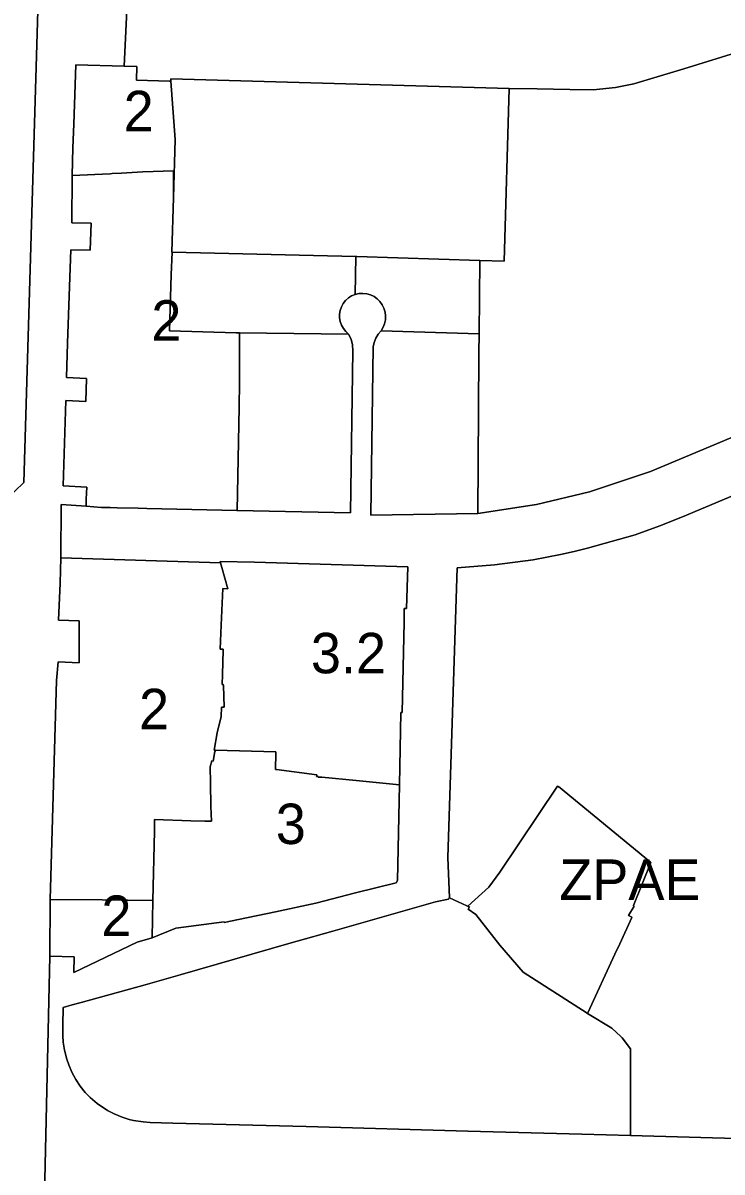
# Model space of a CAD drawing. Extents: x 598968 to 613553, y 4409678 to 4430833.
# Drawn here: x 607715.2 to 607922.7, y 4415445.3 to 4415786.4 of the extents above; entities that cross this region are included whole.
import ezdxf

# ---------------------------------------------------------------- set-up
doc = ezdxf.new("R2010")
doc.units = 0
for name, color, linetype in [('1', 7, 'Continuous'), ('ZONA 2. CARRERS DE CASES. Cases de trast', 7, 'Continuous'), ("ZONA 3. ILLES  D'EDIFICIS ENTRE MITGERES. EIXAMPLE.", 7, 'Continuous'), ('ZONA 3.2. Volumentría específica - ANNEX III B', 7, 'Continuous'), ('Zona de Protecció arquològica-etnoògica', 7, 'Continuous')]:
    doc.layers.add(name, color=color, linetype=linetype)

msp = doc.modelspace()

# ---------------------------------------------------------------- linework, layer by layer
at = {"layer": '1'}
for points in [[(607714.9485, 4415838.4282), (607720.9184, 4415833.4684), (607715.4891, 4415649.9805), (607710.1092, 4415644.8405), (607679.8495, 4415645.5899), (607674.8196, 4415650.8997), (607675.5894, 4415689.7193), (607677.1093, 4415729.6889), (607678.8091, 4415770.7584), (607679.859, 4415798.6881), (607681.1189, 4415834.1777), (607686.7188, 4415839.3877)], [(607850.2624, 4415640.8173), (607867.6185, 4415643.5047), (607883.4383, 4415647.215), (607901.4656, 4415653.2752), (607957.6759, 4415676.7834), (607977.337, 4415685.0662), (607978.3535, 4415685.4948), (607979.827, 4415686.1162), (607979.3077, 4415687.4699), (607939.6372, 4415781.6243), (607929.6005, 4415778.452), (607911.4256, 4415772.8482), (607896.5278, 4415768.3637), (607891.1428, 4415767.2436), (607884.4372, 4415766.6161), (607877.527, 4415766.7217), (607867.8281, 4415766.9182), (607859.5557, 4415766.9957), (607858.0621, 4415715.7316), (607850.8255, 4415715.9577), (607850.5948, 4415694.1575), (607850.5948, 4415694.1535), (607850.5476, 4415688.474), (607850.4452, 4415671.3681)], [(607859.5557, 4415766.9957), (607759.0694, 4415769.8512), (607759.1181, 4415769.1588), (607760.3394, 4415751.7915), (607759.8571, 4415734.5967), (607759.4032, 4415718.4153), (607759.4031, 4415718.4118), (607759.4472, 4415718.4107), (607813.9919, 4415717.107), (607814.2717, 4415717.0994), (607850.8106, 4415715.9582), (607850.8255, 4415715.9577), (607858.0621, 4415715.7316)], [(607813.9919, 4415717.107), (607759.4472, 4415718.4107), (607759.2115, 4415711.6107), (607758.7407, 4415695.0522), (607778.4594, 4415694.4725), (607779.4146, 4415694.4613), (607811.8723, 4415694.0812), (607811.0269, 4415694.8282), (607810.3186, 4415695.7063), (607809.7676, 4415696.6906), (607809.3894, 4415697.7535), (607809.1946, 4415698.8647), (607809.1888, 4415699.9928), (607809.3723, 4415701.1059), (607809.7397, 4415702.1726), (607810.2807, 4415703.1626), (607810.9799, 4415704.0479), (607811.8177, 4415704.8034), (607812.7702, 4415705.4079), (607813.8105, 4415705.8441)], [(607850.8255, 4415715.9577), (607850.8106, 4415715.9582), (607814.2717, 4415717.0994), (607813.9919, 4415717.107), (607813.8105, 4415705.8441), (607814.9448, 4415706.093), (607816.1047, 4415706.1507), (607817.2582, 4415706.0158), (607818.3733, 4415705.6916), (607819.4194, 4415705.1874), (607820.3677, 4415704.5169), (607821.1918, 4415703.6988), (607821.8692, 4415702.7555), (607822.381, 4415701.7131), (607822.7133, 4415700.6003), (607822.8567, 4415699.4479), (607822.8075, 4415698.2877), (607822.5668, 4415697.1516), (607822.1414, 4415696.071), (607821.543, 4415695.0757), (607850.5948, 4415694.1575)], [(607811.8723, 4415694.0812), (607779.4146, 4415694.4613), (607779.414, 4415694.4154), (607779.4894, 4415694.4134), (607779.4429, 4415679.6677), (607779.3983, 4415672.3714), (607778.8384, 4415641.7117), (607778.7075, 4415641.7145), (607778.7069, 4415641.6731), (607812.4293, 4415641.0105), (607813.1772, 4415689.1329), (607813.0335, 4415690.8502), (607812.5941, 4415692.5164)], [(607850.5948, 4415694.1575), (607821.543, 4415695.0757), (607820.6452, 4415694.0359), (607819.935, 4415692.8601), (607819.4325, 4415691.5815), (607819.1521, 4415690.2367), (607818.4838, 4415640.3137), (607850.2624, 4415640.8173), (607850.4452, 4415671.3681), (607850.5476, 4415688.474), (607850.5948, 4415694.1535)], [(607841.8091, 4415526.6614), (607841.6892, 4415526.7156), (607841.5147, 4415526.2931), (607837.7086, 4415525.5441), (607825.8596, 4415522.1511), (607807.1774, 4415516.834), (607796.6484, 4415513.7925), (607794.1727, 4415513.084), (607761.8213, 4415503.8268), (607751.4964, 4415500.8964), (607732.4577, 4415495.6232), (607729.8331, 4415494.8962), (607727.139, 4415494.15), (607726.994, 4415488.8423), (607727.0498, 4415487.2224), (607727.0513, 4415485.7209), (607727.1748, 4415483.8285), (607727.5235, 4415481.4596), (607728.1793, 4415478.8123), (607728.7794, 4415477.0565), (607729.677, 4415474.9753), (607730.9118, 4415472.708), (607732.2131, 4415470.7706), (607733.7103, 4415468.921), (607735.1613, 4415467.4093), (607737.2501, 4415465.5989), (607740.3061, 4415463.5422), (607742.2788, 4415462.5132), (607744.6516, 4415461.5368), (607746.7199, 4415460.8947), (607748.0225, 4415460.583), (607750.9173, 4415460.1328), (607753.0081, 4415460.0083), (607759.7376, 4415459.8246), (607799.272, 4415458.7451), (607847.2243, 4415457.4357), (607881.1347, 4415456.5097), (607895.5419, 4415456.1136), (607895.5433, 4415481.8895), (607893.0988, 4415485.1171), (607892.7279, 4415485.4795), (607890.0388, 4415488.017), (607882.8078, 4415492.3427), (607882.6799, 4415492.4192), (607863.689, 4415504.5863), (607856.8012, 4415512.6671), (607849.6392, 4415521.7158), (607847.3692, 4415523.3558), (607847.7192, 4415523.9958), (607847.5739, 4415524.06), (607847.2749, 4415524.1922), (607846.9408, 4415524.34)]]:
    msp.add_lwpolyline(points, close=True, dxfattribs=at)
for points in [[(607720.8462, 4415403.14), (607723.2095, 4415509.3223), (607723.2794, 4415526.2021), (607725.1992, 4415591.1814), (607725.6692, 4415596.8013), (607731.8431, 4415596.4696), (607731.902, 4415608.9244), (607725.7891, 4415609.0912), (607726.1991, 4415620.101), (607726.4194, 4415627.6606), (607726.5133, 4415643.4598), (607733.9189, 4415642.9509), (607733.9911, 4415645.0097), (607734.1189, 4415648.6508), (607727.139, 4415649.0407), (607727.9389, 4415674.3504), (607733.8608, 4415674.0016), (607734.0788, 4415680.8605), (607728.1388, 4415681.1304), (607728.3988, 4415691.4002), (607729.0011, 4415708.1973), (607729.3601, 4415719.0602), (607735.1701, 4415719.0022), (607735.4184, 4415726.9878), (607729.6887, 4415727.1298), (607729.8386, 4415741.1196), (607729.9586, 4415749.3295), (607730.2686, 4415756.3995), (607730.5185, 4415762.2594), (607730.8785, 4415773.9893), (607745.2756, 4415773.6219), (607745.9995, 4415790.2407)], [(607745.9995, 4415790.2407), (607745.2756, 4415773.6219), (607749.0029, 4415773.5268), (607748.8778, 4415769.4693), (607758.7482, 4415769.1498), (607759.1181, 4415769.1588), (607759.0694, 4415769.8512), (607859.5557, 4415766.9957), (607867.8281, 4415766.9182), (607877.527, 4415766.7217), (607884.4372, 4415766.6161), (607891.1428, 4415767.2436), (607896.5278, 4415768.3637), (607911.4256, 4415772.8482), (607929.6005, 4415778.452)], [(607957.6759, 4415676.7834), (607901.4656, 4415653.2752), (607883.4383, 4415647.215), (607867.6185, 4415643.5047), (607850.2624, 4415640.8173), (607818.4838, 4415640.3137), (607819.1521, 4415690.2367), (607819.4325, 4415691.5815), (607819.935, 4415692.8601), (607820.6452, 4415694.0359), (607821.543, 4415695.0757), (607822.1414, 4415696.071), (607822.5668, 4415697.1516), (607822.8075, 4415698.2877), (607822.8567, 4415699.4479), (607822.7133, 4415700.6003), (607822.381, 4415701.7131), (607821.8692, 4415702.7555), (607821.1918, 4415703.6988), (607820.3677, 4415704.5169), (607819.4194, 4415705.1874), (607818.3733, 4415705.6916), (607817.2582, 4415706.0158), (607816.1047, 4415706.1507), (607814.9448, 4415706.093), (607813.8105, 4415705.8441), (607812.7702, 4415705.4079), (607811.8177, 4415704.8034), (607810.9799, 4415704.0479), (607810.2807, 4415703.1626), (607809.7397, 4415702.1726), (607809.3723, 4415701.1059), (607809.1888, 4415699.9928), (607809.1946, 4415698.8647), (607809.3894, 4415697.7535), (607809.7676, 4415696.6906), (607810.3186, 4415695.7063), (607811.0269, 4415694.8282), (607811.8723, 4415694.0812), (607812.5941, 4415692.5164), (607813.0335, 4415690.8502), (607813.1772, 4415689.1329), (607812.4293, 4415641.0105), (607778.7069, 4415641.6731), (607778.7075, 4415641.7145), (607751.9387, 4415642.2812), (607749.3987, 4415642.3612), (607743.1888, 4415642.5011), (607741.0788, 4415642.541), (607738.5189, 4415642.601), (607733.9189, 4415642.9509), (607726.5133, 4415643.4598), (607726.4194, 4415627.6606), (607773.8654, 4415626.1772), (607773.7723, 4415626.5077), (607783.9282, 4415626.3198), (607829.4189, 4415624.9979), (607829.0682, 4415612.5473), (607828.3297, 4415612.5839), (607828.349, 4415608.4981), (607827.7291, 4415581.7184), (607827.4091, 4415581.7184), (607826.9662, 4415560.1971), (607826.3682, 4415531.8139), (607826.0282, 4415531.1139), (607813.9684, 4415528.1837), (607802.1185, 4415525.1035), (607790.2087, 4415522.4834), (607779.1692, 4415520.2224), (607774.9488, 4415519.3431), (607774.9188, 4415519.6031), (607760.559, 4415517.6729), (607753.5391, 4415514.8028), (607749.1292, 4415513.5427), (607730.2594, 4415504.5525), (607730.4094, 4415509.1624), (607723.2095, 4415509.3223), (607720.8462, 4415403.14)], [(608010.5843, 4415452.8771), (607895.5419, 4415456.1136), (607881.1347, 4415456.5097), (607847.2243, 4415457.4357), (607799.272, 4415458.7451), (607759.7376, 4415459.8246), (607753.0081, 4415460.0083), (607750.9173, 4415460.1328), (607748.0225, 4415460.583), (607746.7199, 4415460.8947), (607744.6516, 4415461.5368), (607742.2788, 4415462.5132), (607740.3061, 4415463.5422), (607737.2501, 4415465.5989), (607735.1613, 4415467.4093), (607733.7103, 4415468.921), (607732.2131, 4415470.7706), (607730.9118, 4415472.708), (607729.677, 4415474.9753), (607728.7794, 4415477.0565), (607728.1793, 4415478.8123), (607727.5235, 4415481.4596), (607727.1748, 4415483.8285), (607727.0513, 4415485.7209), (607727.0498, 4415487.2224), (607726.994, 4415488.8423), (607727.139, 4415494.15), (607729.8331, 4415494.8962), (607732.4577, 4415495.6232), (607751.4964, 4415500.8964), (607761.8213, 4415503.8268), (607794.1727, 4415513.084), (607796.6484, 4415513.7925), (607807.1774, 4415516.834), (607825.8596, 4415522.1511), (607837.7086, 4415525.5441), (607841.5147, 4415526.2931), (607841.6892, 4415526.7156), (607841.8091, 4415526.6614), (607841.8092, 4415526.6656), (607841.3392, 4415538.6455), (607844.0589, 4415624.6545), (607855.1687, 4415625.5247), (607866.6686, 4415627.0449), (607874.7733, 4415628.6307), (607878.8224, 4415629.4766), (607882.8284, 4415630.4701), (607896.9382, 4415634.4704), (607904.3046, 4415637.104), (607911.018, 4415639.8355), (607986.087, 4415671.3665)], [(607986.087, 4415671.3665), (607911.018, 4415639.8355), (607904.3046, 4415637.104), (607896.9382, 4415634.4704), (607882.8284, 4415630.4701), (607878.8224, 4415629.4766), (607874.7733, 4415628.6307), (607866.6686, 4415627.0449), (607855.1687, 4415625.5247), (607844.0589, 4415624.6545), (607841.3392, 4415538.6455), (607841.8092, 4415526.6656), (607841.8091, 4415526.6614), (607846.9408, 4415524.34), (607847.2749, 4415524.1922), (607853.4781, 4415529.847), (607856.7414, 4415534.2892), (607873.8877, 4415559.827), (607874.1406, 4415559.6193), (607874.1987, 4415559.7058), (607901.5408, 4415537.2536), (607901.5258, 4415537.2166), (607901.5797, 4415537.1723), (607896.4108, 4415524.4253), (607896.3941, 4415524.3842), (607896.5607, 4415524.2632), (607896.621, 4415524.2194), (607895.0161, 4415521.4282), (607895.9186, 4415520.9267), (607895.8971, 4415520.88), (607895.9574, 4415520.8453), (607892.3575, 4415513.0421), (607890.9241, 4415509.9352), (607882.9198, 4415492.5855), (607882.8078, 4415492.3427), (607890.0388, 4415488.017), (607892.7279, 4415485.4795), (607893.0988, 4415485.1171), (607895.5433, 4415481.8895), (607895.5419, 4415456.1136), (608010.5843, 4415452.8771)]]:
    msp.add_lwpolyline(points, dxfattribs=at)
at = {"layer": 'ZONA 2. CARRERS DE CASES. Cases de trast'}
for points in [[(607745.2756, 4415773.6219), (607730.8785, 4415773.9893), (607730.5185, 4415762.2594), (607730.2686, 4415756.3995), (607729.9586, 4415749.3295), (607729.8386, 4415741.1196), (607741.0785, 4415741.6898), (607741.6886, 4415741.7238), (607744.4884, 4415741.8799), (607750.7684, 4415742.2), (607759.8679, 4415742.5132), (607759.8571, 4415734.5967), (607760.3394, 4415751.7915), (607759.1181, 4415769.1588), (607758.7482, 4415769.1498), (607748.8778, 4415769.4693), (607749.0029, 4415773.5268)], [(607759.8571, 4415734.5967), (607759.8679, 4415742.5132), (607750.7684, 4415742.2), (607744.4884, 4415741.8799), (607741.6886, 4415741.7238), (607741.0785, 4415741.6898), (607729.8386, 4415741.1196), (607729.6887, 4415727.1298), (607735.4184, 4415726.9878), (607735.1701, 4415719.0022), (607729.3601, 4415719.0602), (607729.0011, 4415708.1973), (607728.3988, 4415691.4002), (607728.1388, 4415681.1304), (607734.0788, 4415680.8605), (607733.8608, 4415674.0016), (607727.9389, 4415674.3504), (607727.139, 4415649.0407), (607734.1189, 4415648.6508), (607733.9911, 4415645.0097), (607733.9189, 4415642.9509), (607738.5189, 4415642.601), (607741.0788, 4415642.541), (607743.1888, 4415642.5011), (607749.3987, 4415642.3612), (607751.9387, 4415642.2812), (607778.7075, 4415641.7145), (607778.8384, 4415641.7117), (607779.3983, 4415672.3714), (607779.4429, 4415679.6677), (607779.4894, 4415694.4134), (607779.414, 4415694.4154), (607779.4146, 4415694.4613), (607778.4594, 4415694.4725), (607758.7407, 4415695.0522), (607759.2115, 4415711.6107), (607759.4472, 4415718.4107), (607759.4031, 4415718.4118), (607759.4032, 4415718.4153)], [(607773.8654, 4415626.1772), (607726.4194, 4415627.6606), (607726.1991, 4415620.101), (607725.7891, 4415609.0912), (607731.902, 4415608.9244), (607731.8431, 4415596.4696), (607725.6692, 4415596.8013), (607725.1992, 4415591.1814), (607723.2794, 4415526.2021), (607738.7292, 4415526.0724), (607753.7689, 4415525.8532), (607754.1987, 4415546.5124), (607754.269, 4415549.9024), (607764.9889, 4415549.5726), (607769.2045, 4415549.4973), (607771.1388, 4415549.4627), (607771.0114, 4415553.7981), (607770.8588, 4415560.7825), (607770.7587, 4415565.6225), (607771.2387, 4415567.3325), (607771.6687, 4415567.2825), (607772.2087, 4415570.1725), (607772.2123, 4415570.1724), (607772.2687, 4415570.4725), (607772.2766, 4415570.5081), (607771.9398, 4415570.5176), (607772.8798, 4415575.7175), (607774.0044, 4415580.488), (607774.1697, 4415583.2974), (607774.8997, 4415583.3275), (607774.6908, 4415589.6893), (607774.6785, 4415590.063), (607774.5921, 4415590.0565), (607774.3096, 4415590.0352), (607774.4197, 4415593.0073), (607774.6108, 4415600.1922), (607774.6197, 4415600.5285), (607773.993, 4415600.5483), (607773.7097, 4415600.5572), (607774.0197, 4415607.6272), (607774.5037, 4415618.5251), (607776.0296, 4415618.4571), (607774.252, 4415624.8057)], [(607753.7689, 4415525.8532), (607738.7292, 4415526.0724), (607723.2794, 4415526.2021), (607723.2095, 4415509.3223), (607730.4094, 4415509.1624), (607730.2594, 4415504.5525), (607749.1292, 4415513.5427), (607753.5391, 4415514.8028)]]:
    msp.add_lwpolyline(points, close=True, dxfattribs=at)
at = {"layer": "ZONA 3. ILLES  D'EDIFICIS ENTRE MITGERES. EIXAMPLE."}
for points in [[(607715.4891, 4415649.9805), (607720.9184, 4415833.4684), (607714.9485, 4415838.4282), (607686.7188, 4415839.3877), (607681.1189, 4415834.1777), (607679.859, 4415798.6881), (607678.8091, 4415770.7584), (607677.1093, 4415729.6889), (607675.5894, 4415689.7193), (607674.8196, 4415650.8997), (607679.8495, 4415645.5899), (607710.1092, 4415644.8405)], [(607826.9662, 4415560.1971), (607814.1364, 4415561.4965), (607803.8967, 4415562.5261), (607802.8767, 4415562.5461), (607802.8806, 4415562.6902), (607802.3897, 4415562.7005), (607802.393, 4415562.8597), (607802.3995, 4415563.1682), (607790.4938, 4415564.7418), (607790.2196, 4415564.778), (607790.3038, 4415569.6605), (607790.3096, 4415569.9979), (607772.2766, 4415570.5081), (607772.2687, 4415570.4725), (607772.2123, 4415570.1724), (607772.2087, 4415570.1725), (607771.6687, 4415567.2825), (607771.2387, 4415567.3325), (607770.7587, 4415565.6225), (607770.8588, 4415560.7825), (607771.0114, 4415553.7981), (607771.1388, 4415549.4627), (607769.2045, 4415549.4973), (607764.9889, 4415549.5726), (607754.269, 4415549.9024), (607754.1987, 4415546.5124), (607753.7689, 4415525.8532), (607753.5391, 4415514.8028), (607760.559, 4415517.6729), (607774.9188, 4415519.6031), (607774.9488, 4415519.3431), (607779.1692, 4415520.2224), (607790.2087, 4415522.4834), (607802.1185, 4415525.1035), (607813.9684, 4415528.1837), (607826.0282, 4415531.1139), (607826.3682, 4415531.8139)]]:
    msp.add_lwpolyline(points, close=True, dxfattribs=at)
at = {"layer": 'ZONA 3.2. Volumentría específica - ANNEX III B'}
msp.add_lwpolyline([(607826.9662, 4415560.1971), (607827.4091, 4415581.7184), (607827.7291, 4415581.7184), (607828.349, 4415608.4981), (607828.3297, 4415612.5839), (607829.0682, 4415612.5473), (607829.4189, 4415624.9979), (607783.9282, 4415626.3198), (607773.7723, 4415626.5077), (607773.8654, 4415626.1772), (607774.252, 4415624.8057), (607776.0296, 4415618.4571), (607774.5037, 4415618.5251), (607774.0197, 4415607.6272), (607773.7097, 4415600.5572), (607773.993, 4415600.5483), (607774.6197, 4415600.5285), (607774.6108, 4415600.1922), (607774.4197, 4415593.0073), (607774.3096, 4415590.0352), (607774.5921, 4415590.0565), (607774.6785, 4415590.063), (607774.6908, 4415589.6893), (607774.8997, 4415583.3275), (607774.1697, 4415583.2974), (607774.0044, 4415580.488), (607772.8798, 4415575.7175), (607771.9398, 4415570.5176), (607772.2766, 4415570.5081), (607790.3096, 4415569.9979), (607790.3038, 4415569.6605), (607790.2196, 4415564.778), (607790.4938, 4415564.7418), (607802.3995, 4415563.1682), (607802.393, 4415562.8597), (607802.3897, 4415562.7005), (607802.8806, 4415562.6902), (607802.8767, 4415562.5461), (607803.8967, 4415562.5261), (607814.1364, 4415561.4965)], close=True, dxfattribs=at)
at = {"layer": 'Zona de Protecció arquològica-etnoògica'}
msp.add_lwpolyline([(607882.8078, 4415492.3427), (607882.9198, 4415492.5855), (607890.9241, 4415509.9352), (607892.3575, 4415513.0421), (607895.9574, 4415520.8453), (607895.8971, 4415520.88), (607895.9186, 4415520.9267), (607895.0161, 4415521.4282), (607896.621, 4415524.2194), (607896.5607, 4415524.2632), (607896.3941, 4415524.3842), (607896.4108, 4415524.4253), (607901.5797, 4415537.1723), (607901.5258, 4415537.2166), (607901.5408, 4415537.2536), (607874.1987, 4415559.7058), (607874.1406, 4415559.6193), (607873.8877, 4415559.827), (607856.7414, 4415534.2892), (607853.4781, 4415529.847), (607847.2749, 4415524.1922), (607847.5739, 4415524.06), (607847.7192, 4415523.9958), (607847.3692, 4415523.3558), (607849.6392, 4415521.7158), (607856.8012, 4415512.6671), (607863.689, 4415504.5863), (607882.6799, 4415492.4192)], close=True, dxfattribs=at)

# ---------------------------------------------------------------- texts
at = {"layer": 'ZONA 2. CARRERS DE CASES. Cases de trast'}
for p in [(607745.089, 4415754.293), (607753.3142, 4415692.1124), (607749.6545, 4415576.7569), (607738.4892, 4415515.3773)]:
    msp.add_text('2', height=12, dxfattribs=at).set_placement(p)
at = {"layer": "ZONA 3. ILLES  D'EDIFICIS ENTRE MITGERES. EIXAMPLE."}
msp.add_text('3', height=12, dxfattribs=at).set_placement((607790.2526, 4415542.6555))
at = {"layer": 'ZONA 3.2. Volumentría específica - ANNEX III B'}
msp.add_text('3.2', height=12, dxfattribs=at).set_placement((607800.6793, 4415593.3524))
at = {"layer": 'Zona de Protecció arquològica-etnoògica'}
msp.add_text('ZPAE', height=12, dxfattribs=at).set_placement((607874.4273, 4415526.0849))

doc.saveas('drawing.dxf')
